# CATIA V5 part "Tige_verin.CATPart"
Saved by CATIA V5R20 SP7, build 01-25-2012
Part number: Tige_verin
Bounding box of the stored display mesh (mm): x -190.75 to 190.75, y -11.856 to 38.28, z 9.716 to 113.813
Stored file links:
  F:\Travaux\Modélisations\CFAO_2011\MMS\MMS_GR2\AA_OK\tquattrone\Catia\Tige_verin.CATPart
  C:\Users\Tom\Documents\Cours 2A\CFAO\Projet thinkmotion\Aileron_citroen.CATProduct
  F:\Travaux\Modélisations\CFAO_2011\MMS\MMS_GR2\AA_OK\tquattrone\Catia\Corps_verin.CATPart
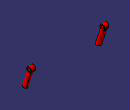
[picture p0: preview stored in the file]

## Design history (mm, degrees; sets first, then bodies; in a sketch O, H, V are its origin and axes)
Parameters
  Diametre_trou_tige = 14 mm
  Rayon_tige_verin = 10.75 mm
Set1
  Plane1 "Plan_verin": linked copy from another document
  Point1 "Point_centre_tige_verin": linked copy from another document
  DatumCurve1: linked copy from another document
  Plane2 "Plan_sym": linked copy from another document
Body1 (main body)
  Sketch1 on Plane1, origin (180, 0, 0), H (0, 1, 0), V (0, 0, 1)
    circle A1 centre (27.0678, 102.635) radius 7
    point P1 (27.0678, 102.635)
    reference projected point E1 (27.0678, 102.635) from Point1
    line L1 (14.3361, 97.0172) -> (34.7751, 90.2332)
    line L2 (34.7751, 90.2332) -> (37.7181, 99.0999)
    arc A2 centre (27.0678, 102.635) radius 11.2217 from (37.7181, 99.0999) to (16.1098, 105.0535) ccw
    point P5 (27.0678, 102.635)
    line L3 (16.1098, 105.0535) -> (14.3361, 97.0172)
    reference projected point E2 (27.0678, 102.635) from Point1
    radius A1 = 7 {= Diametre_trou_tige /2}
    length L1 = 21.5354
    coincidence: P1 E1, P5 E2
    perpendicularity: L2 L1
    tangency: A2 L2, L3 A2
  Pad1: profile Sketch1, direction (1, 0, 0), length 10.75 {= Rayon_tige_verin}, mirrored extent
  Sketch2 on Plane1, origin (180, 0, 0), H (0, 1, 0), V (0, 0, 1)
    line L1 (34.4288, 90.3968) -> (8.476, 9.6782)
    line L2 (8.476, 9.6782) -> (-1.6042, 13.4134)
    line L3 (-1.6042, 13.4134) -> (24.3486, 94.1321)
    line L4 (24.3486, 94.1321) -> (34.4288, 90.3968)
    length L4 = 10.75 {= Rayon_tige_verin}
    parallelism: L4 L2, L1 L3
  Shaft1: profile Sketch2, axis Sketch2.L3, angle 360
  Mirror1: of the body so far, about Plane2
